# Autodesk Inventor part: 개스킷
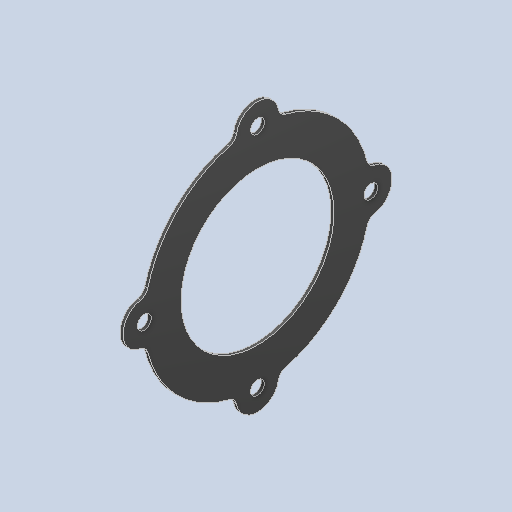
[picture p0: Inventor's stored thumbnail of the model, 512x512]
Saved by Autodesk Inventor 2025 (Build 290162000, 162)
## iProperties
Created: 2024-08
Part Number: 개스킷
Material: 황동, 연질 노란색
Document SubType Name: Modeling
Designer: samsung
Density: 8.47 g/cm^3
Appearance: 기본값
Author: jhkim
Sending System: Autodesk Inventor 2025
Preprocessor: ST-DEVELOPER v20
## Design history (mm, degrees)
feature "솔리드2"
node "솔리드1"
